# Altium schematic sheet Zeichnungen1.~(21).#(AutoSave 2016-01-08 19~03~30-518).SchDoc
size A4; PageSetup: Record=PageOptions¦CenterHorizontal=True¦CenterVertical=True¦PrintScale=1.00¦XCorrection=1.00¦YCorrection=1.00¦PrintKind=0¦BorderSize=5000000¦LeftOffset=0¦BottomOffset=0¦Orientation=2¦PaperLength=1000¦PaperWidth=1000¦Scale=100¦PaperSource=7¦PrintQuality=-3¦MediaType=1¦DitherType=10¦PrintScaleMode=1¦PaperKind=A4¦PaperIndex=9
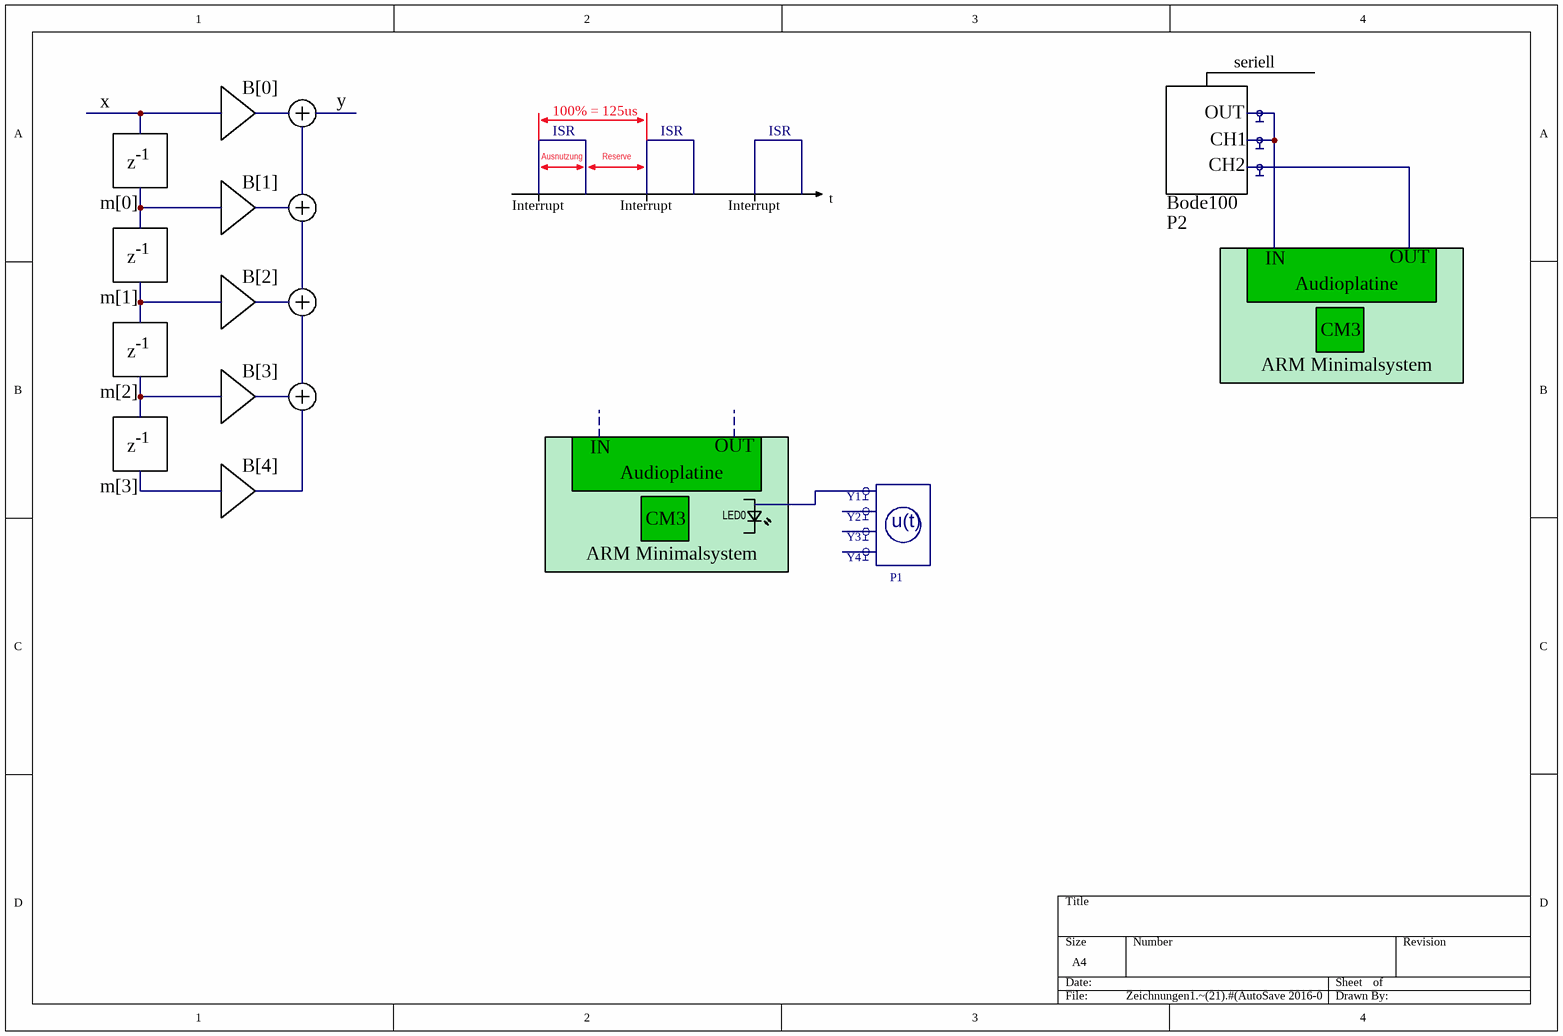
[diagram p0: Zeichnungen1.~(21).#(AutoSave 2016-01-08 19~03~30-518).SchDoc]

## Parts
P1  Oszilloskop4Kanal  (value not drawn)

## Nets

Not connected (* = marked no-connect by the designer): P1 1 2 3 4

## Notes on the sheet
- x
- B[0]
- y
- 100% = 125us
- seriell
- z
- -1
- Ausnutzung
- ISR
- Reserve
- OUT
- CH2
- CH1
- m[0]
- B[1]
- Interrupt
- t
- Bode100
- P2
- m[1]
- B[2]
- IN
- Audioplatine
- B[3]
- ARM Minimalsystem
- CM3
- m[2]
- m[3]
- B[4]
- LED0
